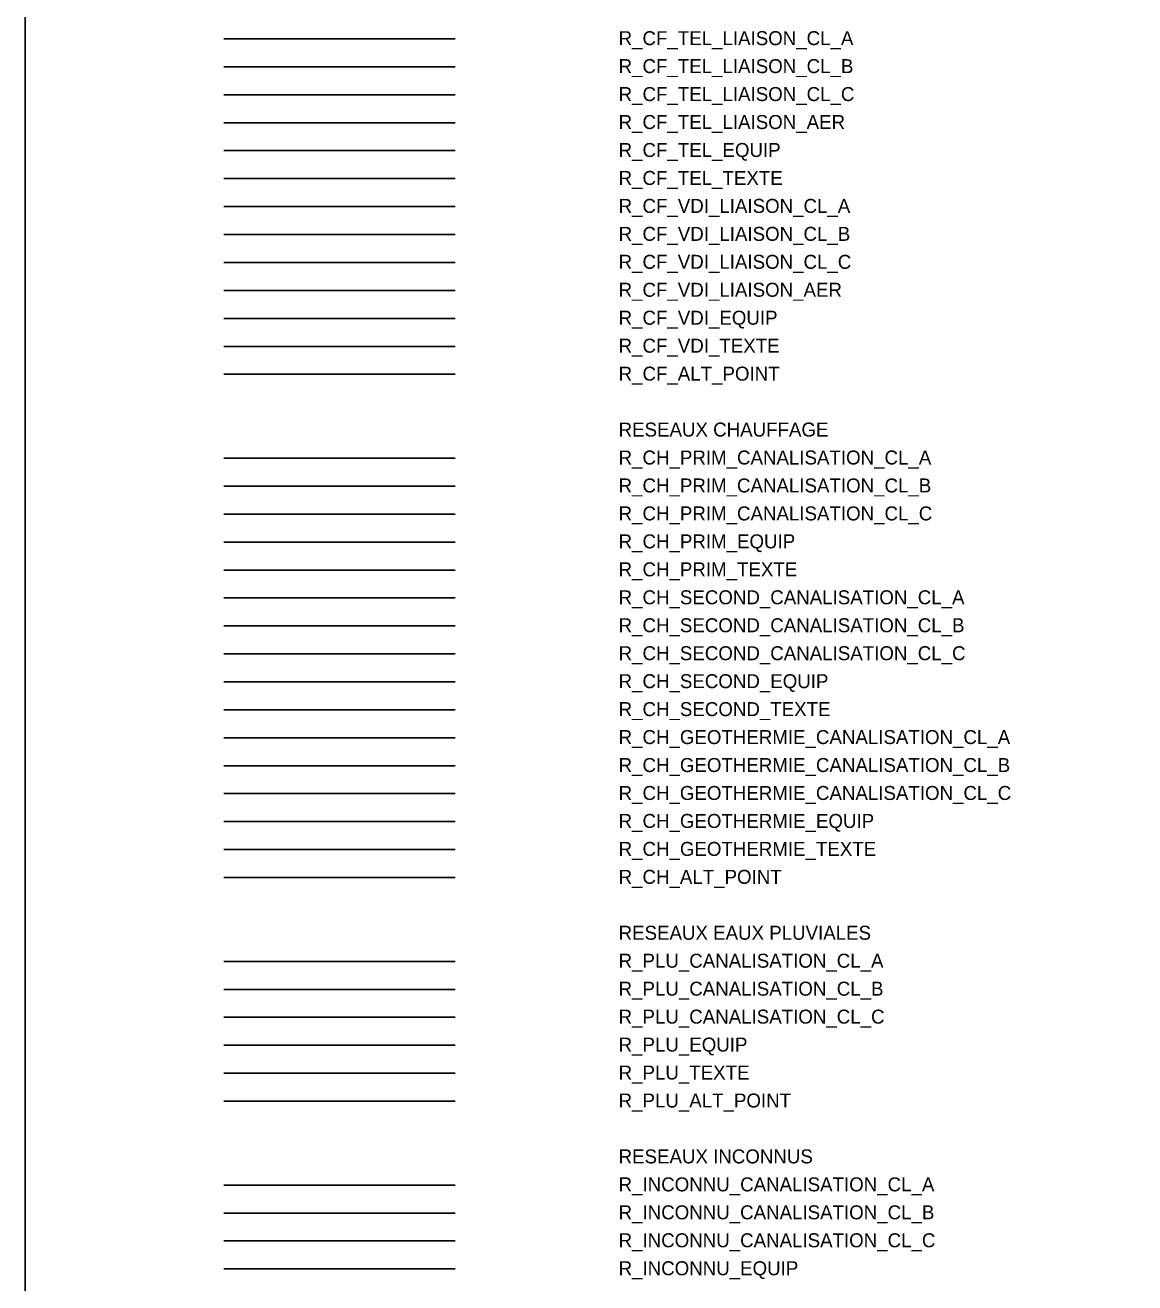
# Model space of a CAD drawing. Extents: x -60 to 214, y -380 to -21.
# Drawn here: x 33.07 to 72.77, y -290.93 to -245.94 of the extents above; entities that cross this region are included whole.
import ezdxf

# ---------------------------------------------------------------- set-up
doc = ezdxf.new("R2010")
doc.units = 0
for name, color, linetype in [('Default', 7, 'Continuous'), ('DH_TEXTE', 7, 'Continuous'), ('R_CF_ALT_POINT', 7, 'Continuous'), ('R_CF_TEL_EQUIP', 7, 'Continuous'), ('R_CF_TEL_LIAISON_CL_A', 7, 'Continuous'), ('R_CF_TEL_LIAISON_CL_B', 7, 'Continuous'), ('R_CF_TEL_LIAISON_CL_C', 7, 'Continuous'), ('R_CF_TEL_TEXTE', 7, 'Continuous'), ('R_CF_VDI_EQUIP', 7, 'Continuous'), ('R_CF_VDI_LIAISON_CL_A', 7, 'Continuous'), ('R_CF_VDI_LIAISON_CL_B', 7, 'Continuous'), ('R_CF_VDI_LIAISON_CL_C', 7, 'Continuous'), ('R_CF_VDI_TEXTE', 7, 'Continuous'), ('R_CH_ALT_POINT', 7, 'Continuous'), ('R_CH_GEOTHERMIE_CANALISATION_CL_A', 7, 'Continuous'), ('R_CH_GEOTHERMIE_CANALISATION_CL_B', 7, 'Continuous'), ('R_CH_GEOTHERMIE_CANALISATION_CL_C', 7, 'Continuous'), ('R_CH_GEOTHERMIE_EQUIP', 7, 'Continuous'), ('R_CH_GEOTHERMIE_TEXTE', 7, 'Continuous'), ('R_CH_PRIM_CANALISATION_CL_A', 7, 'Continuous'), ('R_CH_PRIM_CANALISATION_CL_B', 7, 'Continuous'), ('R_CH_PRIM_CANALISATION_CL_C', 7, 'Continuous'), ('R_CH_PRIM_EQUIP', 7, 'Continuous'), ('R_CH_PRIM_TEXTE', 7, 'Continuous'), ('R_CH_SECOND_CANALISATION_CL_A', 7, 'Continuous'), ('R_CH_SECOND_CANALISATION_CL_B', 7, 'Continuous'), ('R_CH_SECOND_CANALISATION_CL_C', 7, 'Continuous'), ('R_CH_SECOND_EQUIP', 7, 'Continuous'), ('R_CH_SECOND_TEXTE', 7, 'Continuous'), ('R_INCONNU_CANALISATION_CL_A', 7, 'Continuous'), ('R_INCONNU_CANALISATION_CL_B', 7, 'Continuous'), ('R_INCONNU_CANALISATION_CL_C', 7, 'Continuous'), ('R_INCONNU_EQUIP', 7, 'Continuous'), ('R_PLU_ALT_POINT', 7, 'Continuous'), ('R_PLU_CANALISATION_CL_A', 7, 'Continuous'), ('R_PLU_CANALISATION_CL_B', 7, 'Continuous'), ('R_PLU_CANALISATION_CL_C', 7, 'Continuous'), ('R_PLU_EQUIP', 7, 'Continuous'), ('R_PLU_TEXTE', 7, 'Continuous')]:
    doc.layers.add(name, color=color, linetype=linetype)

msp = doc.modelspace()

# ---------------------------------------------------------------- linework, layer by layer
at = {"layer": 'Default'}
for p, q in [((40.178, -249.429), (48.457, -249.429)), ((40.178, -255.429), (48.457, -255.429))]:
    msp.add_line(p, q, dxfattribs=at)
msp.add_lwpolyline([(114.838, -25.727), (33.073, -25.727), (33.073, -380.216), (114.838, -380.216)], close=True, dxfattribs=at)
at = {"layer": 'R_CF_ALT_POINT'}
msp.add_line((40.178, -258.429), (48.457, -258.429), dxfattribs=at)
at = {"layer": 'R_CF_TEL_EQUIP'}
msp.add_line((40.178, -250.429), (48.457, -250.429), dxfattribs=at)
at = {"layer": 'R_CF_TEL_LIAISON_CL_A'}
msp.add_line((40.178, -246.429), (48.457, -246.429), dxfattribs=at)
at = {"layer": 'R_CF_TEL_LIAISON_CL_B'}
msp.add_line((40.178, -247.429), (48.457, -247.429), dxfattribs=at)
at = {"layer": 'R_CF_TEL_LIAISON_CL_C'}
msp.add_line((40.178, -248.429), (48.457, -248.429), dxfattribs=at)
at = {"layer": 'R_CF_TEL_TEXTE'}
msp.add_line((40.178, -251.429), (48.457, -251.429), dxfattribs=at)
at = {"layer": 'R_CF_VDI_EQUIP'}
msp.add_line((40.178, -256.429), (48.457, -256.429), dxfattribs=at)
at = {"layer": 'R_CF_VDI_LIAISON_CL_A'}
msp.add_line((40.178, -252.429), (48.457, -252.429), dxfattribs=at)
at = {"layer": 'R_CF_VDI_LIAISON_CL_B'}
msp.add_line((40.178, -253.429), (48.457, -253.429), dxfattribs=at)
at = {"layer": 'R_CF_VDI_LIAISON_CL_C'}
msp.add_line((40.178, -254.429), (48.457, -254.429), dxfattribs=at)
at = {"layer": 'R_CF_VDI_TEXTE'}
msp.add_line((40.178, -257.429), (48.457, -257.429), dxfattribs=at)
at = {"layer": 'R_CH_ALT_POINT'}
msp.add_line((40.178, -276.429), (48.457, -276.429), dxfattribs=at)
at = {"layer": 'R_CH_GEOTHERMIE_CANALISATION_CL_A'}
msp.add_line((40.178, -271.429), (48.457, -271.429), dxfattribs=at)
at = {"layer": 'R_CH_GEOTHERMIE_CANALISATION_CL_B'}
msp.add_line((40.178, -272.429), (48.457, -272.429), dxfattribs=at)
at = {"layer": 'R_CH_GEOTHERMIE_CANALISATION_CL_C'}
msp.add_line((40.178, -273.429), (48.457, -273.429), dxfattribs=at)
at = {"layer": 'R_CH_GEOTHERMIE_EQUIP'}
msp.add_line((40.178, -274.429), (48.457, -274.429), dxfattribs=at)
at = {"layer": 'R_CH_GEOTHERMIE_TEXTE'}
msp.add_line((40.178, -275.429), (48.457, -275.429), dxfattribs=at)
at = {"layer": 'R_CH_PRIM_CANALISATION_CL_A'}
msp.add_line((40.178, -261.429), (48.457, -261.429), dxfattribs=at)
at = {"layer": 'R_CH_PRIM_CANALISATION_CL_B'}
msp.add_line((40.178, -262.429), (48.457, -262.429), dxfattribs=at)
at = {"layer": 'R_CH_PRIM_CANALISATION_CL_C'}
msp.add_line((40.178, -263.429), (48.457, -263.429), dxfattribs=at)
at = {"layer": 'R_CH_PRIM_EQUIP'}
msp.add_line((40.178, -264.429), (48.457, -264.429), dxfattribs=at)
at = {"layer": 'R_CH_PRIM_TEXTE'}
msp.add_line((40.178, -265.429), (48.457, -265.429), dxfattribs=at)
at = {"layer": 'R_CH_SECOND_CANALISATION_CL_A'}
msp.add_line((40.178, -266.429), (48.457, -266.429), dxfattribs=at)
at = {"layer": 'R_CH_SECOND_CANALISATION_CL_B'}
msp.add_line((40.178, -267.429), (48.457, -267.429), dxfattribs=at)
at = {"layer": 'R_CH_SECOND_CANALISATION_CL_C'}
msp.add_line((40.178, -268.429), (48.457, -268.429), dxfattribs=at)
at = {"layer": 'R_CH_SECOND_EQUIP'}
msp.add_line((40.178, -269.429), (48.457, -269.429), dxfattribs=at)
at = {"layer": 'R_CH_SECOND_TEXTE'}
msp.add_line((40.178, -270.429), (48.457, -270.429), dxfattribs=at)
at = {"layer": 'R_INCONNU_CANALISATION_CL_A'}
msp.add_line((40.178, -287.429), (48.457, -287.429), dxfattribs=at)
at = {"layer": 'R_INCONNU_CANALISATION_CL_B'}
msp.add_line((40.178, -288.429), (48.457, -288.429), dxfattribs=at)
at = {"layer": 'R_INCONNU_CANALISATION_CL_C'}
msp.add_line((40.178, -289.429), (48.457, -289.429), dxfattribs=at)
at = {"layer": 'R_INCONNU_EQUIP'}
msp.add_line((40.178, -290.429), (48.457, -290.429), dxfattribs=at)
at = {"layer": 'R_PLU_ALT_POINT'}
msp.add_line((40.178, -284.429), (48.457, -284.429), dxfattribs=at)
at = {"layer": 'R_PLU_CANALISATION_CL_A'}
msp.add_line((40.178, -279.429), (48.457, -279.429), dxfattribs=at)
at = {"layer": 'R_PLU_CANALISATION_CL_B'}
msp.add_line((40.178, -280.429), (48.457, -280.429), dxfattribs=at)
at = {"layer": 'R_PLU_CANALISATION_CL_C'}
msp.add_line((40.178, -281.429), (48.457, -281.429), dxfattribs=at)
at = {"layer": 'R_PLU_EQUIP'}
msp.add_line((40.178, -282.429), (48.457, -282.429), dxfattribs=at)
at = {"layer": 'R_PLU_TEXTE'}
msp.add_line((40.178, -283.429), (48.457, -283.429), dxfattribs=at)

# ---------------------------------------------------------------- texts
at = {"layer": 'DH_TEXTE'}
for s, p in [('R_CF_VDI_LIAISON_AER ', (54.301, -255.655)), ('RESEAUX CHAUFFAGE ', (54.301, -260.655)), ('RESEAUX EAUX PLUVIALES', (54.301, -278.655)), ('RESEAUX INCONNUS', (54.301, -286.655))]:
    msp.add_text(s, height=0.5, dxfattribs=at).set_placement(p)
at = {"layer": 'R_CF_ALT_POINT'}
msp.add_text('R_CF_ALT_POINT  ', height=0.5, dxfattribs=at).set_placement((54.301, -258.655))
at = {"layer": 'R_CF_TEL_EQUIP'}
msp.add_text('R_CF_TEL_EQUIP ', height=0.5, dxfattribs=at).set_placement((54.301, -250.655))
at = {"layer": 'R_CF_TEL_LIAISON_CL_A'}
for s, p in [('R_CF_TEL_LIAISON_CL_A ', (54.301, -246.655)), ('R_CF_TEL_LIAISON_AER ', (54.301, -249.655))]:
    msp.add_text(s, height=0.5, dxfattribs=at).set_placement(p)
at = {"layer": 'R_CF_TEL_LIAISON_CL_B'}
msp.add_text('R_CF_TEL_LIAISON_CL_B ', height=0.5, dxfattribs=at).set_placement((54.301, -247.655))
at = {"layer": 'R_CF_TEL_LIAISON_CL_C'}
msp.add_text('R_CF_TEL_LIAISON_CL_C ', height=0.5, dxfattribs=at).set_placement((54.301, -248.655))
at = {"layer": 'R_CF_TEL_TEXTE'}
msp.add_text('R_CF_TEL_TEXTE ', height=0.5, dxfattribs=at).set_placement((54.301, -251.655))
at = {"layer": 'R_CF_VDI_EQUIP'}
msp.add_text('R_CF_VDI_EQUIP ', height=0.5, dxfattribs=at).set_placement((54.301, -256.655))
at = {"layer": 'R_CF_VDI_LIAISON_CL_A'}
msp.add_text('R_CF_VDI_LIAISON_CL_A ', height=0.5, dxfattribs=at).set_placement((54.301, -252.655))
at = {"layer": 'R_CF_VDI_LIAISON_CL_B'}
msp.add_text('R_CF_VDI_LIAISON_CL_B ', height=0.5, dxfattribs=at).set_placement((54.301, -253.655))
at = {"layer": 'R_CF_VDI_LIAISON_CL_C'}
msp.add_text('R_CF_VDI_LIAISON_CL_C ', height=0.5, dxfattribs=at).set_placement((54.301, -254.655))
at = {"layer": 'R_CF_VDI_TEXTE'}
msp.add_text('R_CF_VDI_TEXTE ', height=0.5, dxfattribs=at).set_placement((54.301, -257.655))
at = {"layer": 'R_CH_ALT_POINT'}
msp.add_text('R_CH_ALT_POINT  ', height=0.5, dxfattribs=at).set_placement((54.301, -276.655))
at = {"layer": 'R_CH_GEOTHERMIE_CANALISATION_CL_A'}
msp.add_text('R_CH_GEOTHERMIE_CANALISATION_CL_A ', height=0.5, dxfattribs=at).set_placement((54.301, -271.655))
at = {"layer": 'R_CH_GEOTHERMIE_CANALISATION_CL_B'}
msp.add_text('R_CH_GEOTHERMIE_CANALISATION_CL_B ', height=0.5, dxfattribs=at).set_placement((54.301, -272.655))
at = {"layer": 'R_CH_GEOTHERMIE_CANALISATION_CL_C'}
msp.add_text('R_CH_GEOTHERMIE_CANALISATION_CL_C ', height=0.5, dxfattribs=at).set_placement((54.301, -273.655))
at = {"layer": 'R_CH_GEOTHERMIE_EQUIP'}
msp.add_text('R_CH_GEOTHERMIE_EQUIP ', height=0.5, dxfattribs=at).set_placement((54.301, -274.655))
at = {"layer": 'R_CH_GEOTHERMIE_TEXTE'}
msp.add_text('R_CH_GEOTHERMIE_TEXTE ', height=0.5, dxfattribs=at).set_placement((54.301, -275.655))
at = {"layer": 'R_CH_PRIM_CANALISATION_CL_A'}
msp.add_text('R_CH_PRIM_CANALISATION_CL_A ', height=0.5, dxfattribs=at).set_placement((54.301, -261.655))
at = {"layer": 'R_CH_PRIM_CANALISATION_CL_B'}
msp.add_text('R_CH_PRIM_CANALISATION_CL_B ', height=0.5, dxfattribs=at).set_placement((54.301, -262.655))
at = {"layer": 'R_CH_PRIM_CANALISATION_CL_C'}
msp.add_text('R_CH_PRIM_CANALISATION_CL_C ', height=0.5, dxfattribs=at).set_placement((54.301, -263.655))
at = {"layer": 'R_CH_PRIM_EQUIP'}
msp.add_text('R_CH_PRIM_EQUIP ', height=0.5, dxfattribs=at).set_placement((54.301, -264.655))
at = {"layer": 'R_CH_PRIM_TEXTE'}
msp.add_text('R_CH_PRIM_TEXTE ', height=0.5, dxfattribs=at).set_placement((54.301, -265.655))
at = {"layer": 'R_CH_SECOND_CANALISATION_CL_A'}
msp.add_text('R_CH_SECOND_CANALISATION_CL_A ', height=0.5, dxfattribs=at).set_placement((54.301, -266.655))
at = {"layer": 'R_CH_SECOND_CANALISATION_CL_B'}
msp.add_text('R_CH_SECOND_CANALISATION_CL_B ', height=0.5, dxfattribs=at).set_placement((54.301, -267.655))
at = {"layer": 'R_CH_SECOND_CANALISATION_CL_C'}
msp.add_text('R_CH_SECOND_CANALISATION_CL_C ', height=0.5, dxfattribs=at).set_placement((54.301, -268.655))
at = {"layer": 'R_CH_SECOND_EQUIP'}
msp.add_text('R_CH_SECOND_EQUIP ', height=0.5, dxfattribs=at).set_placement((54.301, -269.655))
at = {"layer": 'R_CH_SECOND_TEXTE'}
msp.add_text('R_CH_SECOND_TEXTE ', height=0.5, dxfattribs=at).set_placement((54.301, -270.655))
at = {"layer": 'R_INCONNU_CANALISATION_CL_A'}
msp.add_text('R_INCONNU_CANALISATION_CL_A ', height=0.5, dxfattribs=at).set_placement((54.301, -287.655))
at = {"layer": 'R_INCONNU_CANALISATION_CL_B'}
msp.add_text('R_INCONNU_CANALISATION_CL_B ', height=0.5, dxfattribs=at).set_placement((54.301, -288.655))
at = {"layer": 'R_INCONNU_CANALISATION_CL_C'}
msp.add_text('R_INCONNU_CANALISATION_CL_C ', height=0.5, dxfattribs=at).set_placement((54.301, -289.655))
at = {"layer": 'R_INCONNU_EQUIP'}
msp.add_text('R_INCONNU_EQUIP ', height=0.5, dxfattribs=at).set_placement((54.301, -290.655))
at = {"layer": 'R_PLU_ALT_POINT'}
msp.add_text('R_PLU_ALT_POINT  ', height=0.5, dxfattribs=at).set_placement((54.301, -284.655))
at = {"layer": 'R_PLU_CANALISATION_CL_A'}
msp.add_text('R_PLU_CANALISATION_CL_A ', height=0.5, dxfattribs=at).set_placement((54.301, -279.655))
at = {"layer": 'R_PLU_CANALISATION_CL_B'}
msp.add_text('R_PLU_CANALISATION_CL_B ', height=0.5, dxfattribs=at).set_placement((54.301, -280.655))
at = {"layer": 'R_PLU_CANALISATION_CL_C'}
msp.add_text('R_PLU_CANALISATION_CL_C ', height=0.5, dxfattribs=at).set_placement((54.301, -281.655))
at = {"layer": 'R_PLU_EQUIP'}
msp.add_text('R_PLU_EQUIP ', height=0.5, dxfattribs=at).set_placement((54.301, -282.655))
at = {"layer": 'R_PLU_TEXTE'}
msp.add_text('R_PLU_TEXTE ', height=0.5, dxfattribs=at).set_placement((54.301, -283.655))

doc.saveas('drawing.dxf')
